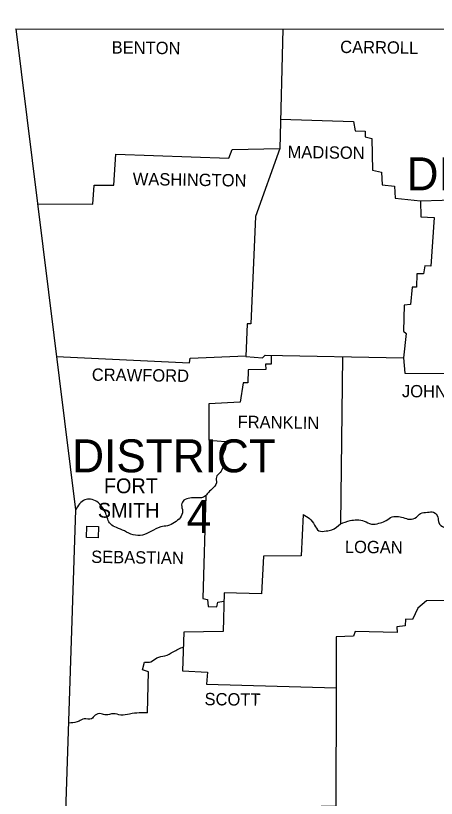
# Model space of a CAD drawing. Extents: x -0.25 to 1.92, y 0 to 0.95.
# Drawn here: x 1.0951 to 1.1614, y 0.6965 to 0.8199 of the extents above; entities that cross this region are included whole.
import ezdxf

# ---------------------------------------------------------------- set-up
doc = ezdxf.new("R2010")
doc.units = 0
doc.layers.add('Default', color=7, linetype='Continuous')

msp = doc.modelspace()

# ---------------------------------------------------------------- linework, layer by layer
at = {"layer": 'Default'}
msp.add_line((1.10377, 0.70837), (1.10343, 0.70833), dxfattribs=at)
for points in [[(1.09511, 0.81784), (1.16886, 0.81779), (1.23365, 0.81792), (1.31002, 0.81909), (1.34545, 0.81992)], [(1.09511, 0.81784), (1.10455, 0.74198), (1.10045, 0.61817)], [(1.1372, 0.81781), (1.13672, 0.79894)], [(1.13684, 0.80359), (1.14835, 0.80321), (1.14861, 0.80176), (1.15019, 0.80171), (1.15014, 0.80083), (1.1512, 0.80054), (1.1513, 0.79554), (1.15273, 0.79523), (1.15283, 0.79325), (1.15481, 0.793), (1.15491, 0.79115), (1.15886, 0.79073), (1.16912, 0.791), (1.1692, 0.81779)], [(1.09854, 0.79022), (1.10724, 0.79019), (1.10745, 0.79318), (1.11059, 0.79318), (1.11087, 0.79805), (1.12869, 0.79743), (1.12921, 0.79878), (1.13672, 0.79894), (1.13289, 0.78825), (1.13214, 0.77131), (1.13159, 0.77129), (1.13134, 0.76618), (1.13401, 0.76595), (1.13442, 0.76636), (1.15618, 0.76595), (1.15641, 0.76353)], [(1.15886, 0.79073), (1.15896, 0.7882), (1.16106, 0.78809), (1.16051, 0.78042), (1.15955, 0.78044), (1.15937, 0.77922), (1.15828, 0.7792), (1.15823, 0.77712), (1.15755, 0.77707), (1.15732, 0.77437), (1.15631, 0.77424), (1.15618, 0.77015), (1.15665, 0.76981), (1.15618, 0.76595)], [(1.15641, 0.76353), (1.20706, 0.76309), (1.20732, 0.76792), (1.21921, 0.76776)], [(1.10154, 0.76614), (1.12247, 0.76514), (1.12257, 0.76589), (1.13134, 0.76629)], [(1.13537, 0.76634), (1.13533, 0.76493), (1.13447, 0.76493), (1.1345, 0.7641), (1.13175, 0.76405), (1.1317, 0.76203), (1.13092, 0.76203), (1.13048, 0.75897), (1.12555, 0.75871), (1.12553, 0.75295), (1.12817, 0.75275)], [(1.14661, 0.76613), (1.14627, 0.73978)], [(1.12508, 0.74427), (1.12459, 0.728), (1.12532, 0.72782), (1.12542, 0.72673), (1.12682, 0.72666), (1.12693, 0.72741), (1.12792, 0.72757)], [(1.14041, 0.74123), (1.1401, 0.73472), (1.13416, 0.73467), (1.13382, 0.72873), (1.12796, 0.72889), (1.12778, 0.72279), (1.12161, 0.72271), (1.1214, 0.71659), (1.12532, 0.71639), (1.12516, 0.71449), (1.14558, 0.71393)], [(1.17039, 0.73425), (1.17018, 0.72769), (1.15981, 0.72764), (1.15844, 0.72647), (1.15763, 0.72466), (1.15652, 0.72471), (1.15647, 0.7237), (1.15514, 0.72354), (1.15519, 0.72261), (1.14858, 0.72277), (1.14832, 0.72204), (1.1456, 0.72194), (1.14558, 0.71393)], [(1.11588, 0.70998), (1.11603, 0.71641), (1.1151, 0.71672), (1.11541, 0.71794)], [(1.14558, 0.71393), (1.14552, 0.69525), (1.14321, 0.6952), (1.14342, 0.69385), (1.14122, 0.69387), (1.14116, 0.69286), (1.13901, 0.69286), (1.13906, 0.69216), (1.1359, 0.69206), (1.13582, 0.68928), (1.13274, 0.68957), (1.13222, 0.66711)]]:
    msp.add_lwpolyline(points, dxfattribs=at)
msp.add_lwpolyline([(1.10628, 0.73763), (1.10633, 0.73939), (1.10815, 0.73934), (1.1081, 0.73757)], close=True, dxfattribs=at)
for points in [[(1.12817, 0.75275), (1.12817, 0.75179), (1.12781, 0.7508), (1.12757, 0.74992), (1.12773, 0.74878), (1.12732, 0.74787), (1.12672, 0.74712), (1.12672, 0.74624), (1.12604, 0.74528), (1.12529, 0.74452), (1.12467, 0.74395), (1.1235, 0.74388), (1.12254, 0.74382), (1.12161, 0.74349), (1.12125, 0.74279), (1.1214, 0.74175), (1.12104, 0.74074), (1.12011, 0.73999), (1.11904, 0.73947), (1.11795, 0.73929), (1.11642, 0.73856), (1.11507, 0.73799), (1.1136, 0.73804), (1.11225, 0.73864), (1.111, 0.73918), (1.11004, 0.73975), (1.10929, 0.74141), (1.10877, 0.74235), (1.10789, 0.74328), (1.10688, 0.74364), (1.106, 0.74354), (1.10455, 0.74198)], [(1.14041, 0.74123), (1.1414, 0.74061), (1.14218, 0.73957), (1.14285, 0.73869), (1.14402, 0.73864), (1.14492, 0.73882), (1.14627, 0.73978)], [(1.14627, 0.73978), (1.1478, 0.74027), (1.14889, 0.7404), (1.15001, 0.74019), (1.15115, 0.73973), (1.15234, 0.73986), (1.15325, 0.74017), (1.15418, 0.74076), (1.15517, 0.74095), (1.15615, 0.74076), (1.15717, 0.74048), (1.15823, 0.74082), (1.15888, 0.74139), (1.15997, 0.74159), (1.16095, 0.74159), (1.16163, 0.74082), (1.16176, 0.73996), (1.16264, 0.73921), (1.16339, 0.73869), (1.16365, 0.73776), (1.16404, 0.73706), (1.16445, 0.73659), (1.16505, 0.73633), (1.16606, 0.73641), (1.16762, 0.7361), (1.1686, 0.73589), (1.16954, 0.73508), (1.17039, 0.73425)], [(1.11541, 0.71794), (1.1164, 0.71802), (1.11736, 0.71864), (1.11863, 0.71895), (1.11992, 0.7196), (1.12153, 0.72037)], [(1.11588, 0.70998), (1.11458, 0.70995), (1.11305, 0.70977), (1.11168, 0.70959), (1.11046, 0.70982), (1.10934, 0.70964), (1.10856, 0.70982), (1.10761, 0.70959), (1.10703, 0.70902), (1.10589, 0.70902), (1.10509, 0.70866), (1.10377, 0.70837)]]:
    msp.add_spline(points, degree=3, dxfattribs=at)

# ---------------------------------------------------------------- texts
for s, rotation, p in [('CARROLL', 359.267, (1.14622, 0.81403)), ('BENTON', 359.2874, (1.11022, 0.81395)), ('MADISON', 359.217, (1.13793, 0.79746)), ('WASHINGTON', 359.2079, (1.11354, 0.7932)), ('CRAWFORD', 359.2748, (1.10709, 0.76234)), ('JOHNSON', 359.2575, (1.15595, 0.75975)), ('FRANKLIN', 359.1782, (1.13006, 0.7549)), ('LOGAN', 359.3076, (1.14696, 0.73519)), ('SEBASTIAN', 359.1959, (1.10699, 0.73361)), ('SCOTT', 359.32, (1.12485, 0.71117))]:
    msp.add_text(s, height=0.001945, rotation=rotation, dxfattribs=at).set_placement(p)
for s, height, p in [('DISTRICT 9', 0.005203, (1.15669, 0.79237)), ('DISTRICT', 0.005203, (1.10401, 0.74789)), ('FORT', 0.002334, (1.10901, 0.7446)), ('SMITH', 0.002334, (1.10805, 0.74074)), ('4', 0.0052, (1.12205, 0.73831))]:
    msp.add_text(s, height=height, dxfattribs=at).set_placement(p)

doc.saveas('drawing.dxf')
